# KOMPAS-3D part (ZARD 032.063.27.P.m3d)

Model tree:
1. Плоскость XY
2. Плоскость ZX
3. Плоскость ZY
4. Ось X
5. Ось Y
6. Ось Z
7. Начало координат
8. Булева операция:1
9. Булева операция:2
10. Булева операция:3
11. Булева операция:4
